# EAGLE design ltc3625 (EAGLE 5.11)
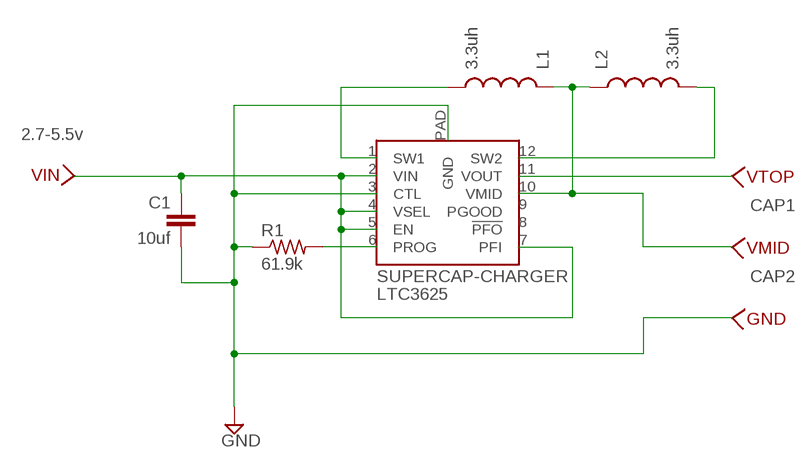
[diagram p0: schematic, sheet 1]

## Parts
C1  10uf  C-EUC1206  [C1206]
GND  WIREPAD-SMD-SMALL-NAMED  [WIREPAD-SMD-SMALL]
L1  3.3uh  INDUCTORCR75_V2  [CR75_V2]
L2  3.3uh  INDUCTORCR75_V2  [CR75_V2]
R1  61.9k  R-US_M0805  [M0805]
SUPERCAP-CHARGER  LTC3625  [DFN12-POWERPAD]
VIN  WIREPAD-SMD-SMALL-NAMED  [WIREPAD-SMD-SMALL]
VMID  WIREPAD-SMD-SMALL-NAMED  [WIREPAD-SMD-SMALL]
VTOP  WIREPAD-SMD-SMALL-NAMED  [WIREPAD-SMD-SMALL]

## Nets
GND: C1.2 GND.1 R1.1 SUPERCAP-CHARGER.3(CTL) SUPERCAP-CHARGER.PAD(GND)
N$2: L1.P$1 L2.P$1 SUPERCAP-CHARGER.10(VMID) VMID.1
N$3: R1.2 SUPERCAP-CHARGER.6(PROG)
N$4: SUPERCAP-CHARGER.11(VOUT) VTOP.1
N$6: L2.P$2 SUPERCAP-CHARGER.12(SW2)
N$7: L1.P$2 SUPERCAP-CHARGER.1(SW1)
VIN: C1.1 SUPERCAP-CHARGER.2(VIN) SUPERCAP-CHARGER.4(VSEL) SUPERCAP-CHARGER.5(EN) SUPERCAP-CHARGER.7(PFI) VIN.1
Unconnected: SUPERCAP-CHARGER.8(!PFO) SUPERCAP-CHARGER.9(PGOOD)

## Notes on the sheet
- 2.7-5.5v
- CAP1
- CAP2

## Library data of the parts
C1 = rcl:C-EU: CAPACITOR, European symbol
GND VIN VMID VTOP = trl:WIREPAD-SMD-SMALL-NAMED
L1 L2 = SparkFun2011-02-20:INDUCTOR: Inductors
R1 = resistor:R-US_: RESISTOR, American symbol
SUPERCAP-CHARGER = trl:LTC3625

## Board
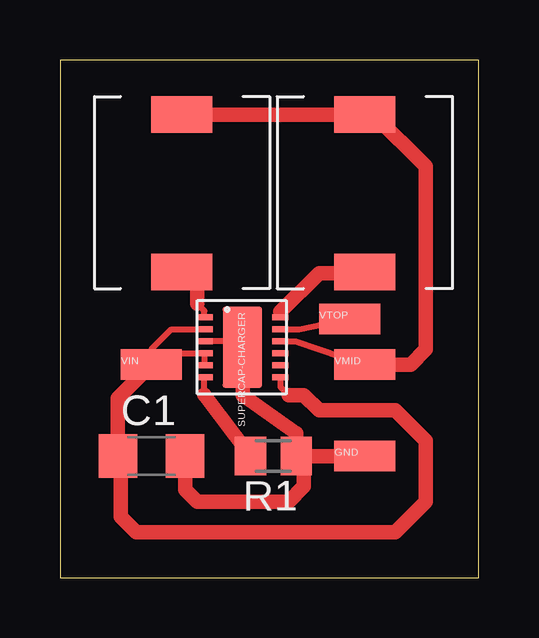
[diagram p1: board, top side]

Size 17.45 x 21.58 mm. Coordinates in mm from the lower left corner, seen from the top.
Outline: 0,0 17.45,0 17.45,21.58 0,21.58 0,0
Copper layers (1*16): Top 0.035mm / dielectric 1.5mm / Bottom 0.035mm
Design rules "default": minimum track width 10mil, minimum drill 0.6mm, track to track 8mil, track to pad 8mil, pad to pad 8mil, via to via 8mil, smd to smd 8mil, copper to edge 40mil, drill to drill 8mil, minimum pad ring 10mil, minimum via ring 8mil, stop-mask expansion 4mil, vias tented up to drill 0mil, thermal gap 10mil

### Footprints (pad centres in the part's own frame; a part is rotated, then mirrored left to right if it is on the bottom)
C1206 = smd 1.6 x 1.8: 1 -1.4,0; 2 1.4,0
WIREPAD-SMD-SMALL = smd 2.54 x 1.27: 1 0,0
CR75_V2 = smd 1.524 x 2.54: P$1 -0.254,0; P$2 6.304,0
M0805 = smd 1.3 x 1.6: 1 -0.95,0; 2 0.95,0
DFN12-POWERPAD = smd 0.25 x 0.67: 1 -0.7,-1.6; 2 -0.2,-1.6; 3 0.3,-1.6; 4 0.8,-1.6; 5 1.3,-1.6; 6 1.8,-1.6; 7 1.8,1.56; 8 1.3,1.56; 9 0.8,1.56; 10 0.3,1.56; 11 -0.2,1.56; 12 -0.7,1.56 | smd 3.38 x 1.65: PAD 0.55,-0.02

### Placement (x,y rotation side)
C1  3.81,5.08 0 top
GND  12.7,5.08 0 top
L1  5.08,19.05 270 top
L2  12.7,19.05 270 top
R1  8.89,5.08 180 top
SUPERCAP-CHARGER  7.62,10.16 270 top
VIN  3.81,8.89 0 top
VMID  12.7,8.89 0 top
VTOP  12.06,10.79 0 top

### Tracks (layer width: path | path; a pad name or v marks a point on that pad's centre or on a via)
GND
  Top 0.254: SUPERCAP-CHARGER.3 7.35,9.86 SUPERCAP-CHARGER.PAD
  Top 0.61: R1.1 GND.1 | R1.1 9.84,6.04 7.62,7.62 7.62,9.59 SUPERCAP-CHARGER.PAD | C1.2 5.21,3.68 5.71,3.17 9.53,3.17 10.16,3.81 10.16,4.76 R1.1
N$2
  Top 0.254: SUPERCAP-CHARGER.10 9.82,9.86 10.79,9.53 VMID.1
  Top 0.61: L1.P$1 L2.P$1 13.08,19.3 15.24,17.14 15.24,9.53 14.61,8.89 VMID.1
N$3
  Top 0.254: 6.02,7.63 SUPERCAP-CHARGER.6
  Top 0.61: R1.2 6.02,7.63
N$4
  Top 0.254: SUPERCAP-CHARGER.11 9.96,10.36 VTOP.1
N$6
  Top 0.254: SUPERCAP-CHARGER.12 9.18,11.09 | 12.65,12.7 L2.P$2
  Top 0.61: 9.18,11.09 10.79,12.7 12.65,12.7
N$7
  Top 0.254: SUPERCAP-CHARGER.1 6.02,11.12 5.71,11.43
  Top 0.61: 5.71,11.43 5.71,12.11 L1.P$2
VIN
  Top 0.254: SUPERCAP-CHARGER.5 SUPERCAP-CHARGER.4 4.28,9.36 VIN.1 3.81,9.53 4.64,10.36 SUPERCAP-CHARGER.2 | SUPERCAP-CHARGER.7 9.18,7.96 9.53,7.62
  Top 0.61: VIN.1 2.41,7.49 C1.1 2.54,4.95 2.54,2.54 3.17,1.91 13.97,1.91 15.24,3.17 15.24,5.71 13.97,6.99 10.79,6.99 10.16,7.62 9.53,7.62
